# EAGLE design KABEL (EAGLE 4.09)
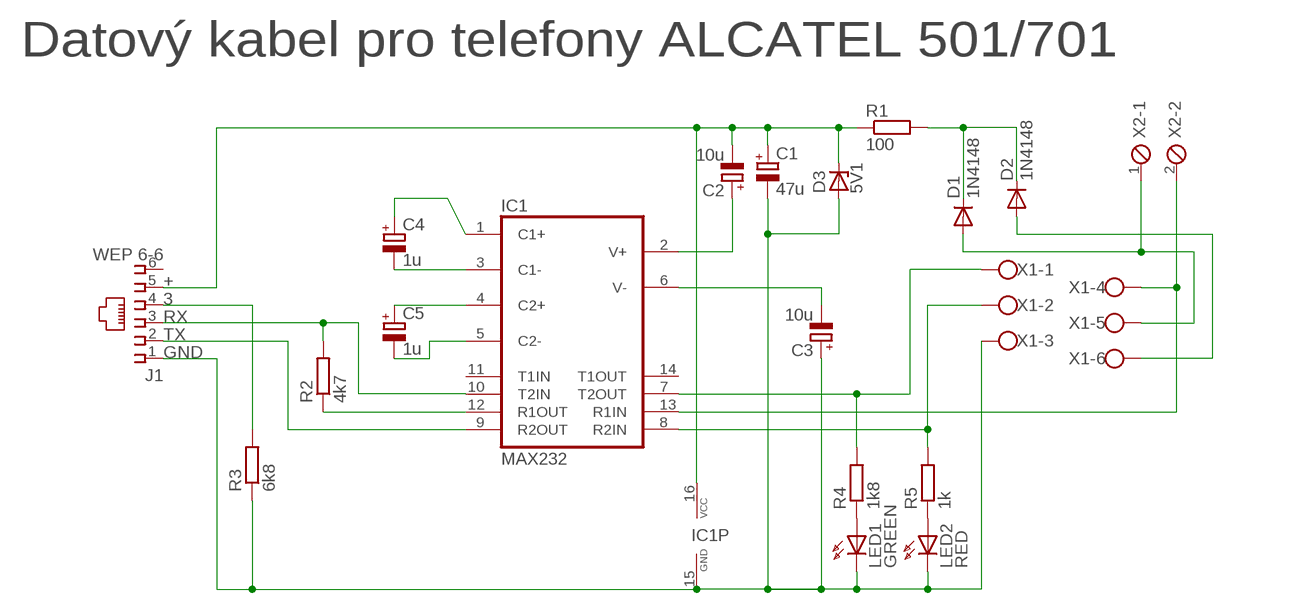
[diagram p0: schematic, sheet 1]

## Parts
C1  47u  CPOL-EUE2-5  [E2-5]
C2  10u  CPOL-EUE2-5  [E2-5]
C3  10u  CPOL-EUE2-5  [E2-5]
C4  1u  CPOL-EUE2-5  [E2-5]
C5  1u  CPOL-EUE2-5  [E2-5]
D1  1N4148  [DO35-10]
D2  1N4148  [DO35-10]
D3  5V1  ZENER-DIODEF126-12  [F126Z12]
IC1  MAX232  [DIL16]
J1  WEP 6-6  520243-3  [520243-3]
LED1  GREEN  LED3MM  [LED3MM]
LED2  RED  LED3MM  [LED3MM]
R1  100  R-EU_0207/15  [0207/15]
R2  4k7  R-EU_0207/15  [0207/15]
R3  6k8  R-EU_0207/15  [0207/15]
R4  1k8  R-EU_0207/15  [0207/15]
R5  1k  R-EU_0207/15  [0207/15]
X1  AK500/6  [AK500/6]
X2  MPT2  [2POL254]

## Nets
3: J1.4 R3.2
+: C1.+ C2.- D3.C IC1.16(VCC) J1.5 R1.1
GND: C1.- C3.+ D3.A IC1.15(GND) J1.1 LED1.K(C) LED2.K(C) R3.1 X1.3
N$1: D2.A X1.6
N$3: D1.A X1.5 X2.1
N$4: D1.C D2.C R1.2
N$5: C3.- IC1.6(V-)
N$8: C5.- IC1.5(C2-)
N$9: IC1.12(R1OUT) R2.1
N$12: C5.+ IC1.4(C2+)
N$13: C2.+ IC1.2(V+)
N$14: IC1.13(R1IN) X1.4 X2.2
N$15: IC1.7(T2OUT) R4.2 X1.1
N$16: IC1.8(R2IN) R5.2 X1.2
N$17: C4.- IC1.3(C1-)
N$18: C4.+ IC1.1(C1+)
N$19: LED1.A R4.1
N$20: LED2.A R5.1
RX: IC1.10(T2IN) J1.3 R2.2
TX: IC1.9(R2OUT) J1.2
Unconnected: IC1.11(T1IN) IC1.14(T1OUT) J1.6

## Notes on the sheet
- Datový kabel pro telefony ALCATEL 501/701

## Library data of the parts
C1-C5 = rcl:CPOL-EU: POLARIZED CAPACITOR, European symbol
D1 D2 = diode:1N4148: DIODE
D3 = diode:ZENER-DIODE: Z-Diode
IC1 = maxim:MAX232: RS232 TRANSEIVER
J1 = con-amp:520243-3: AMP connector
LED1 LED2 = led:LED: LED
R1-R5 = rcl:R-EU_: RESISTOR, European symbol
X1 = con-ptr500:AK500/6: CONNECTOR
X2 = con-phoenix-254:MPT2: PHOENIX CONNECTOR

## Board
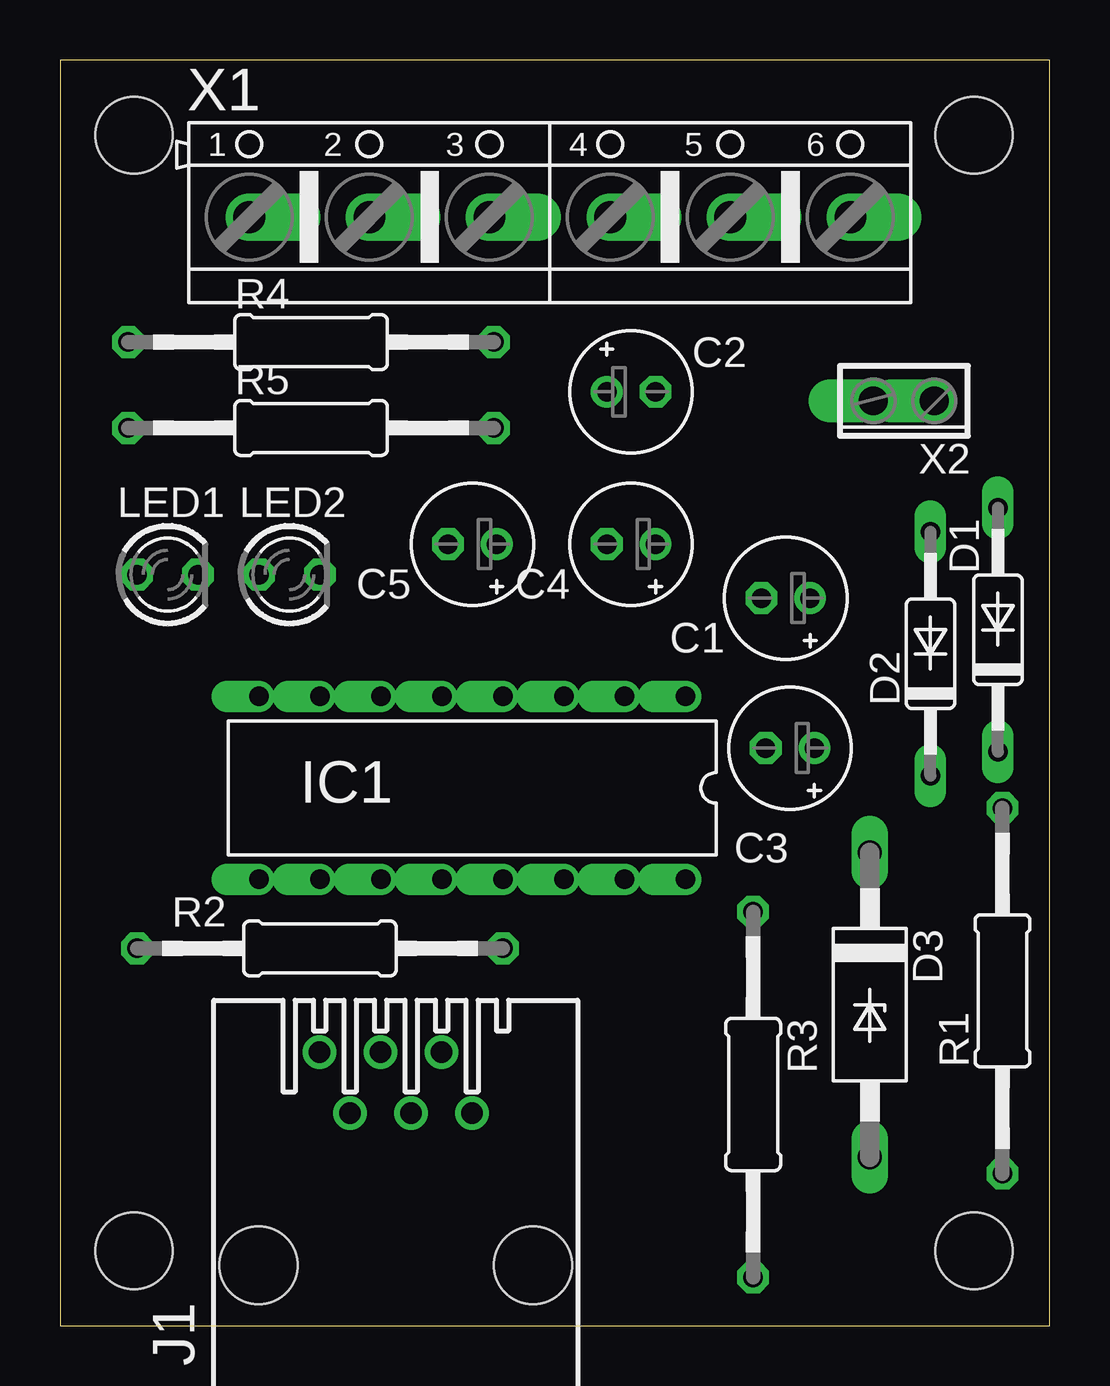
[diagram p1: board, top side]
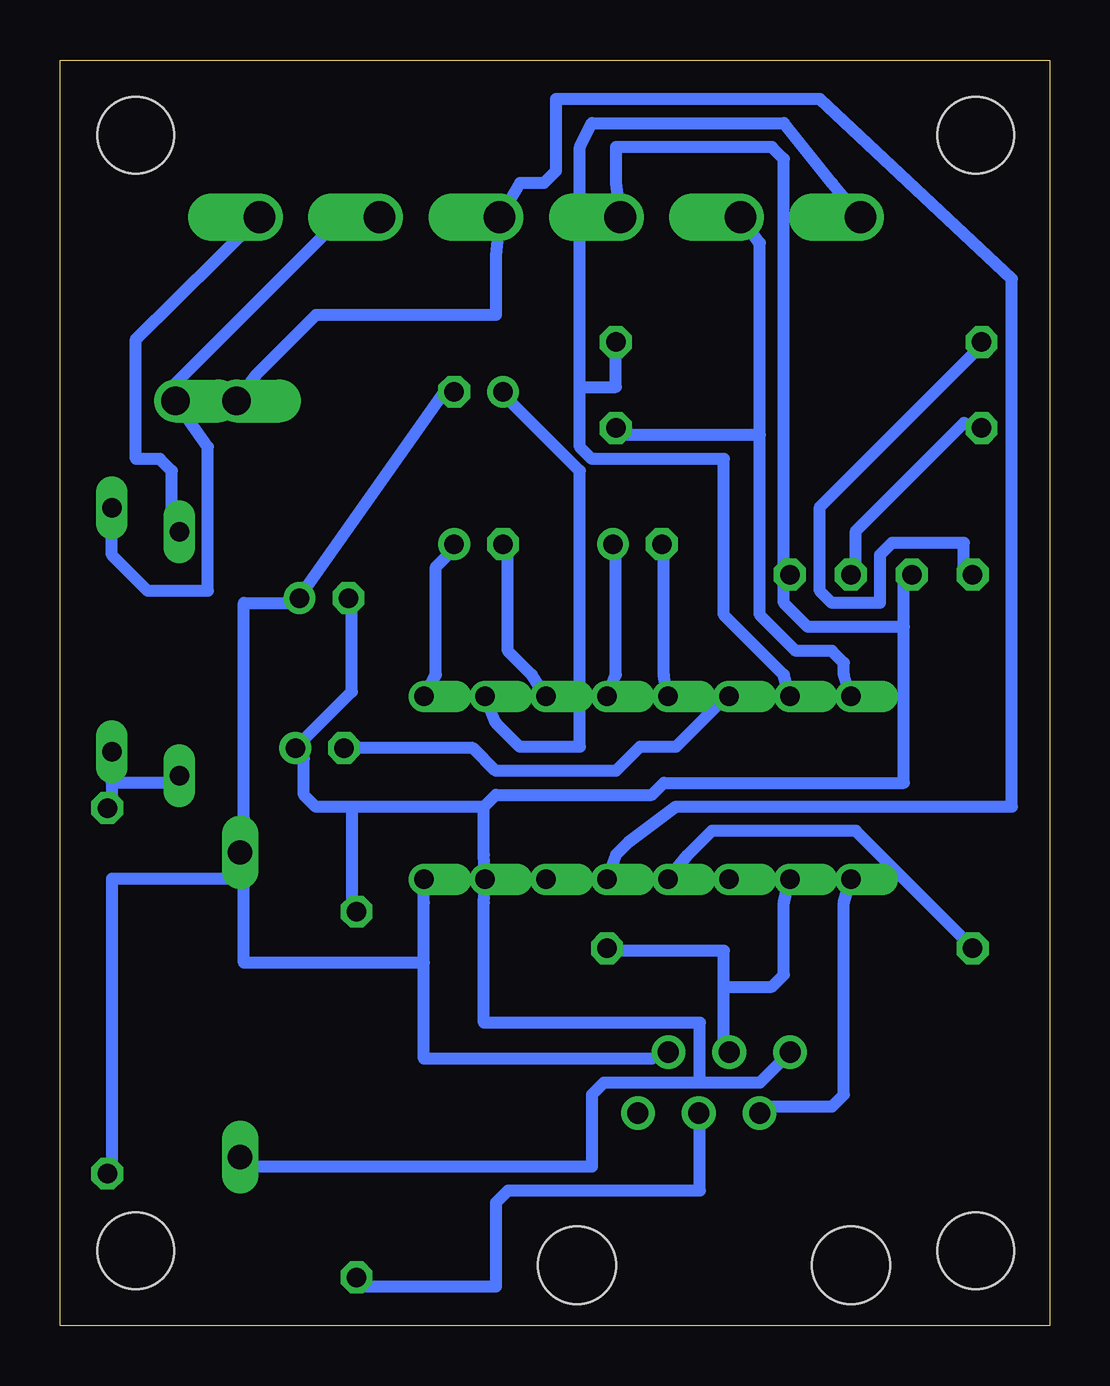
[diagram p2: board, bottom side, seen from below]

Size 41.24 x 52.75 mm. Coordinates in mm from the lower left corner, seen from the top.
Outline: 0,0 41.24,0 41.24,52.75 0,52.75 0,0
Copper layers used: Bottom
Holes 3.2 mm at 3.08,49.62 38.08,49.62 3.08,3.12 38.08,3.12

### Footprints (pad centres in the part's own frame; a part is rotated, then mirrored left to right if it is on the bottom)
E2-5 = drill 0.813 pad 1.27 round: + -1.016,0 | drill 0.813 pad 1.27 octagon: - 1.016,0
DO35-10 = drill 0.813 long: A 5.08,0; C -5.08,0
F126Z12 = drill 1.016 long: A 6.35,0; C -6.35,0
DIL16 = drill 0.813 offset: 1 -8.89,-3.81; 2 -6.35,-3.81; 3 -3.81,-3.81; 4 -1.27,-3.81; 5 1.27,-3.81; 6 3.81,-3.81; 7 6.35,-3.81; 8 8.89,-3.81; 9 8.89,3.81; 10 6.35,3.81; 11 3.81,3.81; 12 1.27,3.81; 13 -1.27,3.81; 14 -3.81,3.81; 15 -6.35,3.81; 16 -8.89,3.81
520243-3 = drill 0.889 round: 1 -3.175,8.89; 2 -1.905,6.35; 3 -0.635,8.89; 4 0.635,6.35; 5 1.905,8.89; 6 3.175,6.35 | hole 3.251: -5.715,0; 5.715,0
LED3MM = drill 0.813 octagon: A -1.27,0; K 1.27,0
0207/15 = drill 0.813 octagon: 1 -7.62,0; 2 7.62,0
AK500/6 = drill 1.321 offset: 1 -12.522,0; 2 -7.518,0; 3 -2.515,0; 4 2.515,0; 5 7.518,0; 6 12.522,0
2POL254 = drill 1.2 offset: 1 -1.27,0; 2 1.27,0

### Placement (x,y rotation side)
C1  30.24,30.32 180 top
C2  23.8,38.92 0 top
C3  30.42,24.07 180 top
C4  23.8,32.57 180 top
C5  17.18,32.57 180 top
D1  39.08,29 90 top
D2  36.27,28 90 top
D3  33.74,13.37 270 top
IC1  17.18,22.41 180 top
J1  13.99,2.51 0 top
LED1  4.48,31.3 0 top
LED2  9.56,31.3 0 top
R1  39.27,13.95 90 top
R2  10.83,15.72 0 top
R3  28.88,9.63 270 top
R4  10.46,40.99 0 top
R5  10.46,37.41 0 top
X1  20.41,46.2 0 top
X2  35.16,38.54 180 top

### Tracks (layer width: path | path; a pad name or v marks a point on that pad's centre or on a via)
3
  Bottom 0.5: R3.2 28.58,1.62 23.08,1.62 23.08,5.12 22.58,5.62 14.58,5.62 14.58,8.62 J1.4
+
  Bottom 0.5: 26.08,15.12 26.08,11.12 16.58,11.12 J1.5 | 26.08,15.12 26.08,17.62 IC1.16 | C2.- 25.08,38.62 25.08,39.12 31.08,30.62 C1.+ 31.58,30.12 33.58,30.12 33.58,21.12 D3.C 33.58,18.62 | 33.58,18.62 39.08,18.62 39.08,6.12 R1.1 | 26.08,15.12 33.58,15.12 33.58,18.62
GND
  Bottom 0.5: C1.- 29.08,30.18 29.08,26.43 C3.+ 31.08,23.62 31.08,22.12 30.58,21.62 29.08,21.62 | 23.58,21.62 29.08,21.62 | 23.58,21.62 23.58,19.62 IC1.15 23.58,17.62 23.58,12.62 14.58,12.62 14.58,10.12 | X1.3 18.08,47.62 18.08,49.12 11.58,49.12 11.08,48.62 11.08,31.62 LED2.K 11.08,31.12 11.08,30.12 10.08,29.12 6.08,29.12 | 6.08,29.12 6.08,31.12 LED1.K | 29.08,21.62 29.08,17.62 R3.1 | 14.58,10.12 12.08,10.12 11.08,11.12 10.58,11.12 J1.1 | 14.58,10.12 18.58,10.12 19.08,9.62 19.08,6.62 33.08,6.62 D3.A | 6.08,29.12 6.08,22.62 16.08,22.62 16.58,22.12 23.08,22.12 23.58,21.62
N$1
  Bottom 0.5: D2.A 36.58,33.12 36.58,35.62 37.08,36.12 38.08,36.12 38.08,41.12 X1.6
N$3
  Bottom 0.5: D1.A 39.08,32.12 37.58,30.62 35.08,30.62 35.08,36.62 X2.1 36.43,39.27 29.58,46.12 28.01,46.12 X1.5
N$4
  Bottom 0.5: 39.08,22.62 36.58,22.62 D2.C | 39.08,22.62 D1.C | 39.08,22.62 39.08,21.62 R1.2
N$5
  Bottom 0.5: C3.- 24.03,24.07 23.08,23.12 18.08,23.12 17.08,24.12 15.58,24.12 13.48,26.22 IC1.6
N$8
  Bottom 0.5: IC1.5 16.08,27.12 16.08,32.12 C5.-
N$9
  Bottom 0.5: R2.1 3.58,16.12 8.08,20.62 14.08,20.62 15.08,19.62 IC1.12
N$12
  Bottom 0.5: IC1.4 18.08,27.12 18.08,32.12 C5.+
N$13
  Bottom 0.5: IC1.2 23.08,25.12 22.08,24.12 19.58,24.12 19.58,35.62 22.58,38.62 C2.+
N$14
  Bottom 0.5: IC1.13 18.08,19.62 17.58,20.12 15.58,21.62 1.58,21.62 1.58,43.62 9.58,51.12 20.58,51.12 20.58,48.12 21.08,47.62 22.08,47.62 X1.4 23.08,44.62 23.08,42.12 30.58,42.12 33.08,39.62 X2.2
N$15
  Bottom 0.5: 19.58,39.12 19.58,36.62 19.08,36.12 13.58,36.12 13.58,29.62 11.08,27.12 IC1.7 | 19.58,39.12 18.08,39.12 R4.2 | 19.58,39.12 19.58,49.12 19.08,50.12 11.08,50.12 9.08,47.62 X1.1
N$16
  Bottom 0.5: 12.08,37.12 12.08,45.12 X1.2 | 12.08,37.12 12.08,29.62 10.58,28.12 9.08,28.12 8.58,27.62 8.58,27.12 IC1.8 | 12.08,37.12 17.58,37.12 R5.2
N$17
  Bottom 0.5: IC1.3 21.58,27.12 22.58,28.12 22.58,32.12 C4.-
N$18
  Bottom 0.5: C4.+ 25.08,32.12 25.58,31.62 25.58,27.12 IC1.1
N$19
  Bottom 0.5: R4.1 3.08,40.62 9.58,34.12 9.58,30.62 9.08,30.12 7.08,30.12 7.08,32.12 6.58,32.62 3.58,32.62 3.58,31.62 LED1.A
N$20
  Bottom 0.5: R5.1 3.58,37.62 8.08,33.12 8.08,31.62 LED2.A
RX
  Bottom 0.5: 13.58,14.12 11.58,14.12 11.08,14.62 11.08,17.62 IC1.10 | 13.58,14.12 13.58,11.62 J1.3 | 13.58,14.12 13.58,15.62 18.08,15.62 R2.2
TX
  Bottom 0.5: IC1.9 8.58,17.62 8.58,9.62 9.08,9.12 11.58,9.12 J1.2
